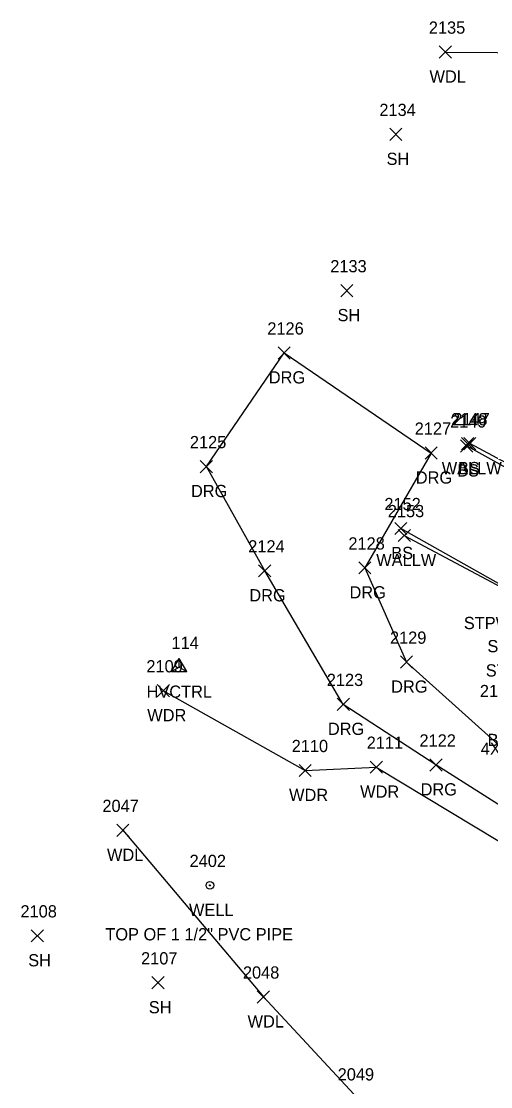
# Model space of a CAD drawing. Extents: x 1885914 to 1887218, y 756253 to 760620.
# Drawn here: x 1886393.6 to 1886470.3, y 760160.7 to 760335 of the extents above; entities that cross this region are included whole.
import ezdxf

# ---------------------------------------------------------------- set-up
doc = ezdxf.new("R2010")
doc.units = 0
for name, color, linetype in [('C_A', 7, 'Continuous'), ('C_I', 7, 'Continuous'), ('CPSM', 7, 'Continuous'), ('L_A', 7, 'Continuous'), ('L_C', 7, 'Continuous'), ('L_I', 7, 'Continuous'), ('L_TIC', 7, 'Continuous'), ('LAWA', 7, 'Continuous'), ('LELB', 7, 'Continuous'), ('LW', 7, 'Continuous'), ('R_A', 7, 'Continuous'), ('R_I', 7, 'Continuous'), ('R_TIC', 7, 'Continuous'), ('RDG', 7, 'Continuous'), ('U_A', 7, 'Continuous'), ('U_C', 7, 'Continuous'), ('U_I', 7, 'Continuous'), ('UWW', 7, 'Continuous')]:
    doc.layers.add(name, color=color, linetype=linetype)

msp = doc.modelspace()

# ---------------------------------------------------------------- linework, layer by layer
at = {"layer": 'CPSM'}
for p, q in [((1886418.15, 760228.62), (1886419.4, 760230.78)), ((1886420.65, 760228.62), (1886419.4, 760230.78)), ((1886419.4, 760229.34), (1886419.4, 760230.78)), ((1886418.15, 760228.62), (1886419.4, 760229.34)), ((1886418.15, 760228.62), (1886420.65, 760228.62)), ((1886419.4, 760229.34), (1886419.4, 760229.34)), ((1886419.4, 760229.34), (1886420.65, 760228.62))]:
    msp.add_line(p, q, dxfattribs=at)
at = {"layer": 'L_TIC'}
for points in [[(1886461.92, 760328.94), (1886463.92, 760330.94)], [(1886463.92, 760328.94), (1886461.92, 760330.94)], [(1886453.83, 760315.48), (1886455.83, 760317.48)], [(1886455.83, 760315.48), (1886453.83, 760317.48)], [(1886445.82, 760289.92), (1886447.82, 760291.92)], [(1886447.82, 760289.92), (1886445.82, 760291.92)], [(1886465.42, 760264.52), (1886467.42, 760266.52)], [(1886467.42, 760264.52), (1886465.42, 760266.52)], [(1886465.56, 760264.9), (1886467.56, 760266.9)], [(1886467.56, 760264.9), (1886465.56, 760266.9)], [(1886465.93, 760264.9), (1886467.93, 760266.9)], [(1886467.93, 760264.9), (1886465.93, 760266.9)], [(1886454.65, 760251.02), (1886456.65, 760253.02)], [(1886456.65, 760251.02), (1886454.65, 760253.02)], [(1886455.21, 760249.87), (1886457.21, 760251.87)], [(1886457.21, 760249.87), (1886455.21, 760251.87)], [(1886415.83, 760224.49), (1886417.83, 760226.49)], [(1886417.83, 760224.49), (1886415.83, 760226.49)], [(1886450.63, 760211.99), (1886452.63, 760213.99)], [(1886452.63, 760211.99), (1886450.63, 760213.99)], [(1886439.02, 760211.45), (1886441.02, 760213.45)], [(1886441.02, 760211.45), (1886439.02, 760213.45)], [(1886409.21, 760201.66), (1886411.21, 760203.66)], [(1886411.21, 760201.66), (1886409.21, 760203.66)], [(1886395.25, 760184.41), (1886397.25, 760186.41)], [(1886397.25, 760184.41), (1886395.25, 760186.41)], [(1886414.96, 760176.73), (1886416.96, 760178.73)], [(1886416.96, 760176.73), (1886414.96, 760178.73)], [(1886432.18, 760174.41), (1886434.18, 760176.41)], [(1886434.18, 760174.41), (1886432.18, 760176.41)]]:
    msp.add_lwpolyline(points, dxfattribs=at)
at = {"layer": 'LAWA'}
for points in [[(1886462.92, 760329.94), (1886488.37, 760329.78), (1886512.78, 760326.43), (1886533.57, 760318.65), (1886557.49, 760303.87)], [(1886416.83, 760225.49), (1886440.02, 760212.45), (1886451.63, 760212.99), (1886475.76, 760198.45), (1886488.7, 760178.57), (1886513.46, 760174.14), (1886520.82, 760161.01), (1886535.34, 760123.1)], [(1886410.21, 760202.66), (1886433.18, 760175.41), (1886448.67, 760158.75), (1886465.42, 760144.55), (1886489.64, 760125.96), (1886497.6, 760121.62), (1886524.44, 760097.09), (1886536.37, 760086.88), (1886546.94, 760096.36), (1886535.34, 760123.1)]]:
    msp.add_lwpolyline(points, dxfattribs=at)
at = {"layer": 'LELB'}
for points in [[(1886466.56, 760265.9), (1886466.42, 760265.52), (1886491.19, 760251.78)], [(1886482.86, 760236.69), (1886455.65, 760252.02)]]:
    msp.add_lwpolyline(points, dxfattribs=at)
at = {"layer": 'LW'}
for points in [[(1886491.7, 760252.64), (1886466.93, 760265.9)], [(1886456.21, 760250.87), (1886475.54, 760240.57)]]:
    msp.add_lwpolyline(points, dxfattribs=at)
at = {"layer": 'R_TIC'}
for points in [[(1886435.58, 760279.74), (1886437.58, 760281.74)], [(1886437.58, 760279.74), (1886435.58, 760281.74)], [(1886459.61, 760263.36), (1886461.61, 760265.36)], [(1886461.61, 760263.36), (1886459.61, 760265.36)], [(1886422.86, 760261.15), (1886424.86, 760263.15)], [(1886424.86, 760261.15), (1886422.86, 760263.15)], [(1886432.4, 760244.1), (1886434.4, 760246.1)], [(1886434.4, 760244.1), (1886432.4, 760246.1)], [(1886448.77, 760244.58), (1886450.77, 760246.58)], [(1886450.77, 760244.58), (1886448.77, 760246.58)], [(1886455.58, 760229.17), (1886457.58, 760231.17)], [(1886457.58, 760229.17), (1886455.58, 760231.17)], [(1886445.24, 760222.26), (1886447.24, 760224.26)], [(1886447.24, 760222.26), (1886445.24, 760224.26)], [(1886460.39, 760212.36), (1886462.39, 760214.36)], [(1886462.39, 760212.36), (1886460.39, 760214.36)]]:
    msp.add_lwpolyline(points, dxfattribs=at)
at = {"layer": 'RDG'}
msp.add_lwpolyline([(1886477.19, 760203.32), (1886461.39, 760213.36), (1886446.24, 760223.26), (1886433.4, 760245.1), (1886423.86, 760262.15), (1886436.58, 760280.74), (1886460.61, 760264.36), (1886449.77, 760245.58), (1886456.58, 760230.17), (1886473.12, 760215.28)], dxfattribs=at)
at = {"layer": 'UWW'}
for radius in [0.625, 0.0833]:
    msp.add_circle((1886424.45, 760193.66), radius, dxfattribs=at)

# ---------------------------------------------------------------- texts
at = {"layer": 'C_A'}
msp.add_text('HVCTRL', height=2, dxfattribs=at).set_placement((1886414.09, 760224.34))
at = {"layer": 'C_I'}
msp.add_text('114', height=2, dxfattribs=at).set_placement((1886418.17, 760232.34))
at = {"layer": 'L_A'}
for s, p in [('WDL', (1886460.34, 760324.94)), ('SH', (1886453.32, 760311.48)), ('SH', (1886445.31, 760285.92)), ('WALLW', (1886462.34, 760260.9)), ('BS', (1886465, 760260.9)), ('BS', (1886464.86, 760260.52)), ('BS', (1886454.09, 760247.02)), ('WALLW', (1886451.63, 760245.87)), ('STPW WALLW', (1886465.95, 760235.57)), ('STPW', (1886469.8, 760231.78)), ('STPW DECK ST', (1886469.53, 760227.81)), ('WDR', (1886414.2, 760220.49)), ('BS', (1886469.84, 760216.44)), ('WDR', (1886437.38, 760207.45)), ('WDR', (1886449, 760207.99)), ('WDL', (1886407.62, 760197.66)), ('SH', (1886394.74, 760180.41)), ('SH', (1886414.45, 760172.73)), ('WDL', (1886430.6, 760170.41))]:
    msp.add_text(s, height=2, dxfattribs=at).set_placement(p)
at = {"layer": 'L_C'}
msp.add_text('4X6 CEDAR', height=2, dxfattribs=at).set_placement((1886468.71, 760215.01))
at = {"layer": 'L_I'}
for s, p in [('2135', (1886460.23, 760332.94)), ('2134', (1886452.14, 760319.48)), ('2133', (1886444.12, 760293.92)), ('2149', (1886463.71, 760268.52)), ('2148', (1886463.87, 760268.9)), ('2147', (1886464.23, 760268.9)), ('2152', (1886452.96, 760255.02)), ('2153', (1886453.52, 760253.87)), ('2109', (1886414.06, 760228.49)), ('2160', (1886468.57, 760224.44)), ('2110', (1886437.81, 760215.45)), ('2111', (1886450.07, 760215.99)), ('2047', (1886406.87, 760205.66)), ('2108', (1886393.48, 760188.41)), ('2107', (1886413.19, 760180.73)), ('2048', (1886429.84, 760178.41)), ('2049', (1886445.33, 760161.75)), ('2049', (1886445.33, 760161.75))]:
    msp.add_text(s, height=2, dxfattribs=at).set_placement(p)
at = {"layer": 'R_A'}
for p in [(1886434.07, 760275.74), (1886458.1, 760259.36), (1886421.35, 760257.15), (1886430.89, 760240.1), (1886447.26, 760240.58), (1886454.07, 760225.17), (1886443.73, 760218.26), (1886458.88, 760208.36)]:
    msp.add_text('DRG', height=2, dxfattribs=at).set_placement(p)
at = {"layer": 'R_I'}
for s, p in [('2126', (1886433.83, 760283.74)), ('2127', (1886457.92, 760267.36)), ('2125', (1886421.17, 760265.15)), ('2128', (1886447.08, 760248.58)), ('2124', (1886430.71, 760248.1)), ('2129', (1886453.88, 760233.17)), ('2123', (1886443.55, 760226.26)), ('2122', (1886458.7, 760216.36))]:
    msp.add_text(s, height=2, dxfattribs=at).set_placement(p)
at = {"layer": 'U_A'}
msp.add_text('WELL', height=2, dxfattribs=at).set_placement((1886421.02, 760188.66))
at = {"layer": 'U_C'}
msp.add_text('TOP OF 1 1/2" PVC PIPE', height=2, dxfattribs=at).set_placement((1886407.35, 760184.66))
at = {"layer": 'U_I'}
msp.add_text('2402', height=2, dxfattribs=at).set_placement((1886421.12, 760196.66))

doc.saveas('drawing.dxf')
